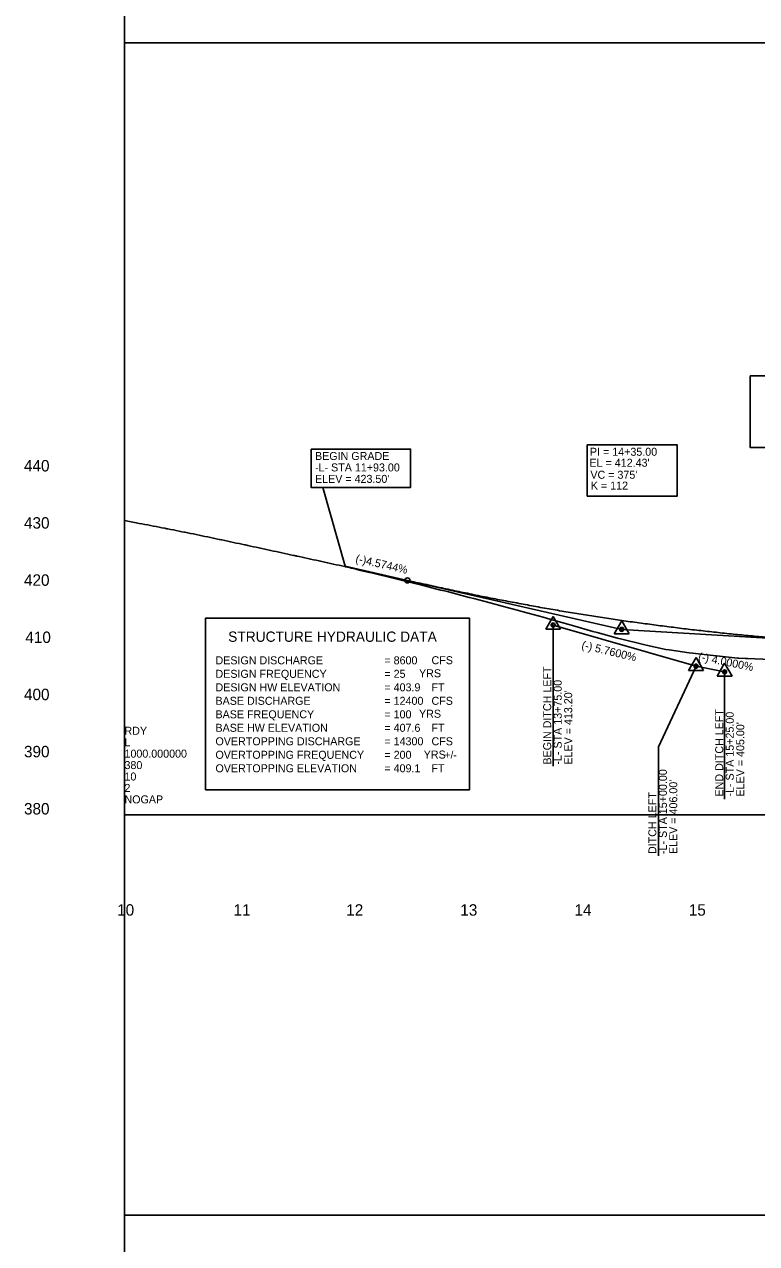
# Model space of a CAD drawing. Extents: x 573767 to 575255, y -54545 to -52045.
# Drawn here: x 573767 to 574408, y -53670 to -52603 of the extents above; entities that cross this region are included whole.
import ezdxf

# ---------------------------------------------------------------- set-up
doc = ezdxf.new("R2010")
doc.units = 0
for name, color, linetype in [('Exist Vertical Profile Ground Line', 7, 'Continuous'), ('Exist Vertical Profile Horizontal Axis Label Major', 7, 'Continuous'), ('Exist Vertical Profile Vertical Axis Label', 7, 'Continuous'), ('Old_Level_4', 7, 'Continuous'), ('Old_Level_63', 7, 'Continuous'), ('Prop Grid Mask', 7, 'Continuous'), ('Prop PFL Structure Hydraulic Data Label CELL', 7, 'Continuous'), ('Prop PFL VPI Symbol CELL', 7, 'Continuous'), ('Prop Vertical Profile Curve Label', 7, 'Continuous'), ('Prop Vertical Profile Ditch Grade Left', 7, 'Continuous'), ('Prop Vertical Profile Ditch Grade Left Label', 7, 'Continuous'), ('Prop Vertical Profile Grade', 7, 'Continuous'), ('Prop Vertical Profile Grade Label', 7, 'Continuous'), ('Prop VPI Ditch Grade Left Label', 7, 'Continuous'), ('Prop VPI Label', 7, 'Continuous'), ('Sheet Layout Profile Border', 7, 'Continuous')]:
    doc.layers.add(name, color=color, linetype=linetype)

msp = doc.modelspace()

# ---------------------------------------------------------------- linework, layer by layer
at = {"layer": 'Exist Vertical Profile Ground Line'}
for points in [[(573854.7, -53037.3), (573865, -53039.3), (573867.5, -53039.8), (573870, -53040.3), (573872.5, -53040.8), (573875, -53041.2), (573876.4, -53041.5), (573877.5, -53041.7), (573880, -53042.2), (573882.5, -53042.7), (573885, -53043.2), (573887.5, -53043.7), (573890, -53044.1), (573891.7, -53044.5), (573891.9, -53044.5), (573892.5, -53044.6), (573895, -53045.1), (573897.5, -53045.6), (573900, -53046.1), (573902.5, -53046.6), (573905, -53047.1), (573907.1, -53047.5), (573907.3, -53047.5), (573907.5, -53047.5), (573910, -53048.1), (573912.5, -53048.6), (573915, -53049.1), (573917.5, -53049.6), (573917.5, -53049.6), (573920, -53050.1), (573922.5, -53050.6), (573925, -53051.2), (573927.5, -53051.7), (573930, -53052.2), (573932.5, -53052.8), (573935, -53053.3), (573937.5, -53053.8), (573937.8, -53053.9), (573939.5, -53054.2), (573940, -53054.3), (573942.5, -53054.9), (573945, -53055.4), (573947.5, -53055.9), (573950, -53056.5), (573952.5, -53057), (573955, -53057.5), (573957.5, -53058.1), (573959.9, -53058.6), (573960, -53058.6), (573960.5, -53058.7), (573961.8, -53059), (573961.8, -53059), (573962.5, -53059.1), (573965, -53059.7), (573967.5, -53060.2), (573970, -53060.7), (573972.5, -53061.3), (573973.6, -53061.5), (573975, -53061.8), (573977.5, -53062.3), (573980, -53062.9), (573982.5, -53063.4), (573985, -53064), (573987.5, -53064.5), (573990, -53065.1), (573992.5, -53065.6), (573995, -53066.2), (573997.5, -53066.7), (574000, -53067.3), (574002.5, -53067.8), (574003.3, -53068), (574004.4, -53068.2), (574005, -53068.3), (574005.5, -53068.5), (574007.5, -53068.9), (574010, -53069.4), (574012.5, -53070), (574015, -53070.5), (574017.5, -53071), (574020, -53071.6), (574022.5, -53072.1), (574025, -53072.7), (574026.2, -53072.9), (574027.4, -53073.2), (574029.9, -53073.8), (574032.4, -53074.3), (574034.9, -53074.9), (574037.4, -53075.4), (574039.9, -53076), (574042.4, -53076.5), (574044.9, -53077.1), (574047.4, -53077.6), (574047.7, -53077.7), (574048, -53077.8), (574049.9, -53078.2), (574052.4, -53078.8), (574053, -53078.9), (574054.9, -53079.4), (574057.4, -53080), (574059.9, -53080.6), (574062.4, -53081.2)], [(574062.4, -53081.2), (574069, -53082.7), (574070.7, -53083.1), (574091, -53088), (574110, -53092.7), (574112.8, -53093.3), (574131.2, -53098.1), (574134.7, -53098.9), (574138.3, -53099.8), (574156.3, -53104.6), (574160.2, -53105.6), (574177.9, -53110.3), (574181.9, -53111.4), (574199.4, -53116.1), (574203.4, -53117.2), (574220.9, -53121.9), (574224.9, -53122.9), (574242.7, -53128), (574246.5, -53129.1), (574264.4, -53134.3), (574268.2, -53135.3), (574286.1, -53140.2), (574289.7, -53141.1), (574307.7, -53145.6), (574311, -53146.3), (574328.3, -53150), (574331.3, -53150.4), (574348.8, -53153.1), (574351.7, -53153.4), (574369.8, -53155.4), (574372.6, -53155.7), (574390.9, -53157.7), (574391, -53157.8), (574391.5, -53157.8), (574392, -53157.8), (574392.1, -53157.8), (574397.9, -53158.1), (574399.8, -53158.1), (574426.7, -53159.3)]]:
    msp.add_lwpolyline(points, dxfattribs=at)
at = {"layer": 'Old_Level_4'}
msp.add_line((574047.7, -53077.2), (574028.2, -53008.4), dxfattribs=at)
for points in [[(574402.2, -52910.8), (574588.2, -52910.8), (574588.2, -52973.5), (574402.2, -52973.5)], [(574259.6, -52971.2), (574338.3, -52971.2), (574338.3, -53015.9), (574259.6, -53015.9)], [(574017.9, -52974.9), (574105, -52974.9), (574105, -53008.4), (574017.9, -53008.4)]]:
    msp.add_lwpolyline(points, close=True, dxfattribs=at)
at = {"layer": 'Old_Level_63'}
for q in [(573854.7, -52044.7), (574854.7, -53294.7), (573854.7, -54544.7)]:
    msp.add_line((573854.7, -53294.7), q, dxfattribs=at)
at = {"layer": 'Prop Grid Mask'}
msp.add_lwpolyline([(573925.6, -53272.9), (574156.5, -53272.9), (574156.5, -53122.6), (573925.6, -53122.6)], close=True, dxfattribs=at)
at = {"layer": 'Prop PFL VPI Symbol CELL'}
for p, q in [((574229.7, -53121.2), (574223.2, -53132.4)), ((574229.7, -53121.2), (574236.2, -53132.4)), ((574229.7, -53128.7), (574229.7, -53252.1)), ((574289.7, -53125.1), (574283.2, -53136.3)), ((574289.7, -53125.1), (574296.2, -53136.3)), ((574223.2, -53132.4), (574236.2, -53132.4)), ((574283.2, -53136.3), (574296.2, -53136.3)), ((574354.7, -53157.2), (574348.2, -53168.4)), ((574354.7, -53157.2), (574361.2, -53168.4)), ((574379.7, -53162.2), (574373.2, -53173.4)), ((574379.7, -53162.2), (574386.2, -53173.4)), ((574354.7, -53164.7), (574321.9, -53235.1)), ((574348.2, -53168.4), (574361.2, -53168.4)), ((574373.2, -53173.4), (574386.2, -53173.4)), ((574379.7, -53169.7), (574379.7, -53280.9)), ((574321.9, -53235.1), (574321.9, -53330.7))]:
    msp.add_line(p, q, dxfattribs=at)
for centre, radius in [((574229.7, -53128.7), 1.75), ((574229.7, -53128.7), 1.2), ((574289.7, -53132.5), 1.75), ((574289.7, -53132.5), 1.2), ((574354.7, -53164.7), 1.75), ((574354.7, -53164.7), 1.2), ((574379.7, -53169.7), 1.75), ((574379.7, -53169.7), 1.2)]:
    msp.add_circle(centre, radius, dxfattribs=at)
at = {"layer": 'Prop Vertical Profile Curve Label'}
msp.add_circle((574102.2, -53089.7), 2.25, dxfattribs=at)
at = {"layer": 'Prop Vertical Profile Ditch Grade Left'}
msp.add_lwpolyline([(574229.7, -53128.7), (574354.7, -53164.7), (574379.7, -53169.7)], dxfattribs=at)
at = {"layer": 'Prop Vertical Profile Grade'}
msp.add_line((574047.7, -53077.2), (574102.2, -53089.7), dxfattribs=at)
msp.add_spline([(574102.2, -53089.7), (574109.7, -53091.4), (574117.2, -53093), (574124.7, -53094.7), (574132.2, -53096.3), (574139.7, -53097.9), (574147.2, -53099.5), (574154.7, -53101), (574162.2, -53102.6), (574169.7, -53104.1), (574177.2, -53105.6), (574184.7, -53107), (574192.2, -53108.4), (574199.7, -53109.8), (574207.2, -53111.2), (574214.7, -53112.6), (574222.2, -53113.9), (574229.7, -53115.2), (574237.2, -53116.5), (574244.7, -53117.7), (574252.2, -53118.9), (574259.7, -53120.1), (574267.2, -53121.3), (574274.7, -53122.5), (574282.2, -53123.6), (574289.7, -53124.7), (574297.2, -53125.8), (574304.7, -53126.8), (574312.2, -53127.8), (574319.7, -53128.8), (574327.2, -53129.8), (574334.7, -53130.7), (574342.2, -53131.7), (574349.7, -53132.6), (574357.2, -53133.4), (574364.7, -53134.3), (574372.2, -53135.1), (574379.7, -53135.9), (574387.2, -53136.7), (574394.7, -53137.4), (574402.2, -53138.1), (574409.7, -53138.8), (574417.2, -53139.5), (574424.7, -53140.1), (574432.2, -53140.8), (574439.7, -53141.4), (574447.2, -53141.9), (574454.7, -53142.5), (574462.2, -53143), (574469.7, -53143.5), (574477.2, -53144)], degree=3, dxfattribs=at)
at = {"layer": 'Prop VPI Ditch Grade Left Label'}
msp.add_circle((574354.7, -53164.7), 0.5, dxfattribs=at)
at = {"layer": 'Prop VPI Label'}
for p in [(574102.2, -53089.7), (574477.2, -53144)]:
    msp.add_line(p, (574289.7, -53132.5), dxfattribs=at)
at = {"layer": 'Sheet Layout Profile Border'}
msp.add_lwpolyline([(573854.7, -52619.7), (573854.7, -53644.7), (575254.7, -53644.7), (575254.7, -52757.2), (575104.7, -52757.2), (575104.7, -52619.7)], close=True, dxfattribs=at)

# ---------------------------------------------------------------- texts
at = {"layer": 'Exist Vertical Profile Horizontal Axis Label Major'}
for s, p in [('10', (573848.3, -53382.9)), ('11', (573950.1, -53382.9)), ('12', (574048.7, -53382.9)), ('13', (574148.5, -53382.9)), ('14', (574248.4, -53382.9)), ('15', (574348.4, -53382.9))]:
    msp.add_text(s, height=10, dxfattribs=at).set_placement(p)
at = {"layer": 'Exist Vertical Profile Vertical Axis Label'}
for s, p in [('440', (573766.8, -52994.4)), ('430', (573766.8, -53044.4)), ('420', (573766.8, -53094.4)), ('410', (573768, -53144.4)), ('400', (573766.8, -53194.4)), ('390', (573766.8, -53244.4)), ('380', (573766.8, -53294.4))]:
    msp.add_text(s, height=10, dxfattribs=at).set_placement(p)
at = {"layer": 'Old_Level_63'}
for s, p in [('RDY', (573854.7, -53224.7)), ('1000.000000', (573854.7, -53244.7)), ('L', (573854.7, -53234.7)), ('380', (573854.7, -53254.7)), ('10', (573854.7, -53264.7)), ('2', (573854.7, -53274.7)), ('NOGAP', (573854.7, -53284.7))]:
    msp.add_text(s, height=7, dxfattribs=at).set_placement(p)
at = {"layer": 'Prop PFL Structure Hydraulic Data Label CELL'}
for s, height, p in [('STRUCTURE HYDRAULIC DATA', 9, (573945.4, -53143.4)), ('DESIGN DISCHARGE', 7, (573934.3, -53163.1)), ('= 8600   ', 7, (574082.1, -53163.1)), ('CFS', 7, (574123.3, -53163)), ('DESIGN FREQUENCY', 7, (573934.3, -53174.9)), ('= 25     ', 7, (574082.1, -53174.9)), ('YRS', 7, (574112.4, -53174.4)), ('DESIGN HW ELEVATION', 7, (573934.3, -53186.7)), ('= 403.9  ', 7, (574082.1, -53186.7)), ('FT', 7, (574123.3, -53186.7)), ('BASE DISCHARGE', 7, (573934.3, -53198.5)), ('= 12400  ', 7, (574082.1, -53198.5)), ('CFS', 7, (574123.3, -53198.5)), ('BASE FREQUENCY', 7, (573934.3, -53210.3)), ('= 100    ', 7, (574082.1, -53210.3)), ('YRS', 7, (574112.4, -53209.8)), ('BASE HW ELEVATION', 7, (573934.3, -53222.1)), ('= 407.6  ', 7, (574082.1, -53222.1)), ('FT', 7, (574123.3, -53222.1)), ('OVERTOPPING DISCHARGE', 7, (573934.3, -53233.9)), ('= 14300  ', 7, (574082.1, -53233.9)), ('CFS', 7, (574123.3, -53233.9)), ('OVERTOPPING FREQUENCY', 7, (573934.3, -53245.7)), ('= 200    ', 7, (574082.1, -53245.7)), ('YRS', 7, (574116.5, -53245.5)), ('+/-', 6.57, (574134.8, -53245.6)), ('OVERTOPPING ELEVATION', 7, (573934.3, -53257.5)), ('= 409.1  ', 7, (574082.1, -53257.5)), ('FT', 7, (574123.3, -53257.5))]:
    msp.add_text(s, height=height, dxfattribs=at).set_placement(p)
at = {"layer": 'Prop PFL VPI Symbol CELL'}
for s, p in [('BEGIN DITCH LEFT', (574228, -53250.8)), ('-L- STA 13+75.00', (574237.2, -53250.8)), ("ELEV = 413.20'", (574246.4, -53250.8)), ('END DITCH LEFT', (574378.5, -53278.7)), ('-L- STA 15+25.00', (574387.7, -53278.7)), ("ELEV = 405.00'", (574396.9, -53278.7)), ('-L- STA 15+00.00 ', (574329.2, -53329)), ("ELEV = 406.00'", (574338.3, -53329)), ('DITCH LEFT', (574320, -53329))]:
    msp.add_text(s, height=7, rotation=90, dxfattribs=at).set_placement(p)
at = {"layer": 'Prop Vertical Profile Curve Label'}
for s, p in [('BEGIN GRADE', (574021.4, -52984.4)), ('-L- STA 11+93.00', (574021.4, -52994.4)), ("ELEV = 423.50'", (574021.4, -53004.4)), ("VC = 375'", (574262.3, -53000.8)), ('K = 112', (574262.7, -53010.3))]:
    msp.add_text(s, height=7, dxfattribs=at).set_placement(p)
at = {"layer": 'Prop Vertical Profile Ditch Grade Left Label'}
for s, rotation, p in [('(-) 5.7600%', 346.4609, (574254.1, -53149.2)), ('(-) 4.0000%', 348.6901, (574356.2, -53159.5))]:
    msp.add_text(s, height=7, rotation=rotation, dxfattribs=at).set_placement(p)
at = {"layer": 'Prop Vertical Profile Grade Label'}
msp.add_text('(-)4.5744%', height=7, rotation=347.117, dxfattribs=at).set_placement((574056.4, -53073.7))
at = {"layer": 'Prop VPI Label'}
for s, p in [('PI = 14+35.00', (574261.9, -52980.7)), ("EL = 412.43'", (574261.5, -52990.3))]:
    msp.add_text(s, height=7, dxfattribs=at).set_placement(p)

doc.saveas('drawing.dxf')
